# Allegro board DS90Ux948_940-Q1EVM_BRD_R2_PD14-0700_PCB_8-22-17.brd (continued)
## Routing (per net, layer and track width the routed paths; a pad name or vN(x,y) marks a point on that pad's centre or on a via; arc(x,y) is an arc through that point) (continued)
BISTC: length 139.4
  TOP w0.178: U1.4 35.65,75.16 34.88,74.39 30.78,74.39 27.86,71.48 27.86,54.41 22.73,49.28 22.73,41.45 26.34,37.85 60.38,37.85 63.27,40.74 63.27,43.84 J14.4 65.66,43.94 65.66,42.19 77.32,30.53 77.32,24.66 S3.2 79.62,22.36 83.58,22.36 90.04,28.83 90.04,31.5
  TOP w0.254: R61.1 S3.2
BISTEN: length 120.6
  TOP w0.178: S3.1 80.54,23.5 79.78,24.26 79.78,30.28 68.22,41.83 68.22,45.52 67.28,46.46 63.35,46.46 J14.2 56.64,39.75 26.29,39.75 24.51,41.53 24.51,49.66 29.15,54.29 29.15,71.23 31.83,73.91 35.03,73.91 36.15,75.04 U1.5
  TOP w0.254: R62.1 S3.1
CAPI2S: length 3.4
  TOP w0.178: U1.2 34.65,75.75 34.37,75.46 v1(33.73,75.46)
  BOTTOM w0.508: v1(33.73,75.46) 33.63,75.56 C10.2
CLK1+: length 79
  TOP w0.152: U1.36 40.15,90.56 arc(40.29,91.27) 40.7,91.87 40.76,91.93 arc(41.23,92.24) 41.78,92.35 41.91,92.35 arc(42.33,92.44) 42.69,92.68 42.75,92.74 arc(42.97,93.07) 43.05,93.46 arc(43.08,93.62) 43.17,93.75 R89.2 43.22,94.26 arc(43.09,94.44) 43.05,94.66 43.05,94.94 arc(43.16,95.48) 43.47,95.94 43.63,96.11 44.04,96.51 arc(44.55,96.86) 45.16,96.98 58.32,96.98 arc(61.45,96.36) 64.1,94.58 67.16,91.52 arc(67.99,90.29) 68.28,88.83 68.28,84.37 arc(68.44,83.55) 68.9,82.86 arc(69.59,82.4) 70.41,82.24 80.08,82.24 arc(81.03,82.42) 81.83,82.96 arc(82.36,83.76) 82.55,84.7 82.55,86.79 arc(82.81,88.12) 83.56,89.24 83.62,89.29 arc(85.03,90.24) 86.7,90.57 92.41,90.57 arc(92.46,90.57) 92.5,90.56 arc(92.63,90.51) 92.74,90.43 arc(92.82,90.31) 92.85,90.16 92.85,89.97 arc(92.82,89.82) 92.74,89.7 92.71,89.67 arc(92.56,89.57) 92.38,89.54 J15.15
CLK1-: length 79
  TOP w0.152: 93.85,92.08 93.09,91.31 arc(92.83,91.14) 92.52,91.08 92.06,91.08 92.06,91.08 86.7,91.08 arc(84.84,90.71) 83.26,89.65 83.2,89.6 arc(82.34,88.31) 82.04,86.79 82.04,84.7 arc(81.89,83.95) 81.47,83.32 arc(80.83,82.89) 80.08,82.74 70.41,82.74 arc(69.79,82.87) 69.26,83.22 arc(68.91,83.75) 68.79,84.37 68.79,88.83 arc(68.46,90.48) 67.52,91.88 64.46,94.94 arc(61.64,96.82) 58.32,97.49 45.16,97.49 arc(44.36,97.33) 43.68,96.87 43.11,96.3 arc(42.69,95.68) 42.54,94.94 42.54,94.69 arc(42.49,94.44) 42.36,94.24 R89.1 42.42,93.75 arc(42.51,93.62) 42.54,93.46 arc(42.5,93.26) 42.39,93.1 42.33,93.03 arc(42.14,92.91) 41.91,92.86 41.78,92.86 arc(41.03,92.71) 40.4,92.29 40.34,92.23 arc(39.82,91.46) 39.64,90.56 39.64,85.95 U1.37
CLK2+: length 64.4
  TOP w0.152: U1.23 42.31,80.78 45.27,80.78 arc(45.84,80.67) 46.33,80.35 47.15,79.52 arc(47.33,79.26) 47.39,78.95 47.39,78.18 arc(47.72,77.38) 48.53,77.05 48.65,77.05 arc(48.88,77) 49.06,76.88 R95.2 49.51,76.87 arc(49.7,77) 49.93,77.05 53.05,77.05 arc(53.22,77.03) 53.38,76.98 arc(53.85,76.73) 54.26,76.39 55.24,75.41 arc(55.4,75.17) 55.46,74.88 55.46,74.72 arc(55.75,73.26) 56.58,72.01 63.75,64.84 65.3,63.3 65.92,62.68 69.84,58.76 arc(75.02,55.3) 81.13,54.08 86.7,54.08 arc(87.49,54.24) 88.17,54.69 arc(88.52,54.93) 88.94,55.01 91.21,55.01 91.71,55.01 91.87,55.01 arc(91.92,55.01) 91.97,55 arc(92.1,54.95) 92.21,54.87 arc(92.29,54.75) 92.32,54.6 92.32,54.41 arc(92.29,54.26) 92.21,54.14 92.18,54.11 arc(92.03,54.01) 91.85,53.98 J16.15
CLK2-: length 64.4
  TOP w0.152: U1.24 42.31,81.29 45.27,81.29 arc(46.04,81.14) 46.69,80.71 47.51,79.88 arc(47.8,79.45) 47.9,78.95 47.9,78.18 arc(48.08,77.74) 48.53,77.55 48.69,77.55 arc(48.88,77.59) 49.04,77.7 R95.1 49.51,77.73 49.52,77.72 arc(49.7,77.6) 49.92,77.55 53.05,77.55 arc(53.32,77.53) 53.57,77.45 arc(54.13,77.15) 54.62,76.75 55.6,75.77 arc(55.87,75.36) 55.97,74.88 55.97,74.72 55.97,74.72 arc(56.22,73.45) 56.94,72.37 57.86,71.45 60.29,69.02 70.2,59.12 arc(75.21,55.77) 81.13,54.59 86.7,54.59 arc(87.3,54.71) 87.81,55.05 arc(88.33,55.4) 88.94,55.52 91.21,55.52 91.54,55.52 91.93,55.52 91.93,55.52 92.39,55.52 arc(92.7,55.58) 92.97,55.75 J16.14
D0+: length 79
  TOP w0.152: J15.3 92.38,104.78 arc(92.56,104.81) 92.71,104.91 92.74,104.94 arc(92.82,105.06) 92.85,105.21 92.85,105.4 arc(92.82,105.55) 92.74,105.67 arc(92.63,105.75) 92.5,105.8 arc(92.46,105.81) 92.41,105.81 89.41,105.81 arc(87.52,105.43) 85.92,104.36 arc(84.44,103.38) 82.7,103.03 40.71,103.03 arc(39.02,102.69) 37.59,101.74 33.18,97.32 32.78,96.93 arc(32.53,96.56) 32.44,96.11 32.44,94.73 arc(32.5,94.45) 32.66,94.21 R80.2 32.59,93.77 arc(32.48,93.62) 32.44,93.43 32.44,93.11 arc(32.51,92.77) 32.7,92.48 33.28,91.9 arc(33.55,91.72) 33.87,91.66 arc(34.47,91.54) 34.98,91.2 35.63,90.55 36.72,89.45 arc(37.04,88.97) 37.16,88.41 37.16,85.94 U1.42
D0-: length 79
  TOP w0.152: U1.43 36.65,85.94 36.65,88.41 arc(36.57,88.78) 36.36,89.09 35.27,90.19 34.62,90.84 arc(34.27,91.07) 33.87,91.15 arc(33.36,91.25) 32.93,91.54 32.34,92.12 arc(32.04,92.58) 31.94,93.11 31.94,93.44 arc(31.9,93.62) 31.8,93.77 R80.1 31.8,94.28 arc(31.9,94.44) 31.94,94.62 31.94,96.11 arc(32.06,96.75) 32.42,97.29 32.82,97.68 33.37,98.23 37.23,102.1 arc(38.83,103.16) 40.71,103.54 82.7,103.54 arc(84.24,103.85) 85.56,104.72 85.56,104.72 arc(87.32,105.9) 89.41,106.32 92.06,106.32 92.06,106.32 92.52,106.32 arc(92.83,106.38) 93.09,106.55 93.85,107.31
D1+: length 79
  TOP w0.152: U1.40 38.15,89.53 arc(37.99,90.34) 37.53,91.03 36.5,92.06 arc(36.12,92.64) 35.98,93.32 35.98,93.42 arc(36.02,93.62) 36.13,93.78 R86.2 36.14,94.26 arc(36.02,94.44) 35.98,94.65 35.98,95.34 arc(36.15,96.18) 36.62,96.89 39.86,100.13 arc(41.09,100.95) 42.54,101.24 66.02,101.24 arc(67.12,101.02) 68.05,100.4 69.98,98.47 arc(70.63,97.5) 70.85,96.36 70.85,95.74 arc(70.97,95.16) 71.3,94.67 71.57,94.4 arc(72.36,93.87) 73.29,93.69 77.99,93.69 arc(79.53,93.99) 80.84,94.87 86.19,100.22 arc(86.76,100.6) 87.43,100.73 92.41,100.73 arc(92.46,100.73) 92.5,100.72 arc(92.63,100.67) 92.74,100.59 arc(92.82,100.47) 92.85,100.32 92.85,100.13 arc(92.82,99.98) 92.74,99.86 92.71,99.83 arc(92.56,99.73) 92.38,99.7 J15.7
D1-: length 79
  TOP w0.152: U1.41 37.64,85.95 37.64,89.53 arc(37.52,90.15) 37.17,90.67 36.14,91.7 arc(35.65,92.44) 35.47,93.32 35.47,93.4 arc(35.43,93.61) 35.31,93.8 R86.1 35.27,94.22 arc(35.42,94.44) 35.47,94.71 35.47,95.34 arc(35.68,96.38) 36.26,97.25 39.5,100.49 arc(40.89,101.42) 42.54,101.75 66.02,101.75 arc(67.32,101.49) 68.41,100.76 70.34,98.83 arc(71.1,97.7) 71.36,96.36 71.36,95.74 arc(71.44,95.35) 71.65,95.03 71.93,94.76 arc(72.55,94.34) 73.29,94.19 77.99,94.19 arc(79.34,94.46) 80.48,95.23 85.84,100.58 arc(86.57,101.07) 87.43,101.24 92.06,101.24 92.06,101.24 92.52,101.24 arc(92.83,101.3) 93.09,101.47 93.85,102.24
D2+: length 79
  TOP w0.152: U1.38 39.15,92.07 arc(39.17,92.16) 39.21,92.25 arc(39.43,92.59) 39.51,92.99 39.51,93.43 arc(39.55,93.62) 39.66,93.77 R88.2 39.67,94.27 arc(39.55,94.44) 39.51,94.64 39.51,94.83 arc(39.65,95.5) 40.02,96.06 40.49,96.53 42.55,98.58 arc(43.1,98.95) 43.75,99.08 60.37,99.08 arc(62.43,98.67) 64.17,97.5 69.68,92 arc(70.74,90.4) 71.12,88.53 71.12,87.95 arc(71.76,86.4) 73.31,85.75 77.97,85.75 arc(78.87,85.93) 79.63,86.44 arc(80.14,87.2) 80.32,88.1 80.32,88.69 arc(80.6,90.11) 81.41,91.32 83.69,93.6 arc(85.96,95.12) 88.64,95.65 92.41,95.65 arc(92.46,95.65) 92.5,95.64 arc(92.63,95.59) 92.74,95.51 arc(92.82,95.39) 92.85,95.24 92.85,95.05 arc(92.82,94.9) 92.74,94.78 92.71,94.75 arc(92.56,94.65) 92.38,94.62 J15.11
D2-: length 79
  TOP w0.152: 93.85,97.16 93.09,96.39 arc(92.83,96.22) 92.52,96.16 92.06,96.16 92.06,96.16 88.64,96.16 arc(85.77,95.59) 83.33,93.96 81.05,91.68 arc(80.14,90.31) 79.81,88.69 79.81,88.1 arc(79.67,87.4) 79.27,86.8 arc(78.68,86.4) 77.97,86.26 73.31,86.26 arc(72.12,86.75) 71.63,87.95 71.63,88.53 arc(71.21,90.6) 70.04,92.35 64.53,97.86 arc(62.62,99.14) 60.37,99.59 43.75,99.59 arc(42.9,99.42) 42.19,98.94 40.13,96.88 39.66,96.42 arc(39.18,95.69) 39.01,94.83 39.01,94.67 arc(38.96,94.44) 38.83,94.25 R88.1 38.85,93.79 arc(38.97,93.61) 39.01,93.41 39.01,92.99 arc(38.96,92.79) 38.85,92.61 arc(38.7,92.38) 38.64,92.12 38.64,85.95 U1.39
D3+: length 79
  TOP w0.152: U1.34 41.15,88.98 arc(41.26,89.53) 41.57,90 41.59,90.02 arc(42.29,90.49) 43.12,90.65 44.28,90.65 arc(45.07,90.81) 45.74,91.26 46.05,91.56 arc(46.44,92.16) 46.58,92.87 46.58,93.39 arc(46.63,93.61) 46.76,93.8 R90.2 46.72,94.29 arc(46.62,94.44) 46.58,94.61 46.58,94.72 arc(46.78,95.18) 47.25,95.38 56.78,95.38 arc(59.18,94.9) 61.22,93.54 64.99,89.77 arc(65.58,88.88) 65.79,87.83 65.79,80.74 arc(66.01,79.65) 66.63,78.73 arc(67.55,78.11) 68.63,77.9 82.25,77.9 arc(83.93,78.59) 84.62,80.26 84.62,82.7 arc(84.83,83.77) 85.44,84.67 arc(86.34,85.28) 87.41,85.49 92.41,85.49 arc(92.46,85.49) 92.5,85.48 arc(92.63,85.43) 92.74,85.35 arc(92.82,85.23) 92.85,85.08 92.85,84.89 arc(92.82,84.74) 92.74,84.62 92.71,84.59 arc(92.56,84.49) 92.38,84.46 J15.19
D3-: length 79
  TOP w0.152: 93.85,87 93.09,86.23 arc(92.83,86.06) 92.52,86 92.06,86 92.06,86 87.41,86 arc(86.15,85.75) 85.08,85.03 arc(84.36,83.96) 84.11,82.7 84.11,80.26 arc(83.57,78.95) 82.25,78.4 68.63,78.4 arc(67.74,78.58) 66.98,79.09 arc(66.48,79.84) 66.3,80.74 66.3,87.83 arc(66.05,89.07) 65.35,90.13 61.58,93.89 arc(59.38,95.37) 56.78,95.89 47.25,95.89 arc(46.42,95.54) 46.08,94.72 46.08,94.62 arc(46.04,94.44) 45.94,94.29 45.86,94.21 R90.1 45.9,93.81 arc(46.03,93.61) 46.08,93.38 46.08,92.86 arc(45.98,92.35) 45.69,91.92 45.38,91.62 arc(44.88,91.28) 44.28,91.16 43.12,91.16 arc(42.1,90.96) 41.24,90.38 41.22,90.36 arc(40.79,89.73) 40.64,88.98 40.64,85.95 U1.35
D4+: length 64.4
  TOP w0.152: U1.29 42.31,83.78 45.04,83.78 arc(45.98,83.97) 46.77,84.5 47.15,84.88 47.71,85.44 arc(48.06,85.96) 48.18,86.58 48.18,87.16 arc(48.33,87.51) 48.68,87.65 arc(48.88,87.61) 49.04,87.5 R92.2 49.51,87.48 arc(49.7,87.61) 49.93,87.65 57.98,87.65 arc(58.11,87.64) 58.24,87.6 58.47,87.5 arc(58.81,87.32) 59.11,87.08 59.98,86.2 60.3,85.89 60.76,85.42 arc(61.19,84.79) 61.34,84.04 61.34,82.89 arc(61.78,80.64) 63.06,78.73 69.49,72.29 71.47,70.32 71.51,70.28 arc(72.96,69.31) 74.66,68.97 84.94,68.97 arc(85.63,69.11) 86.22,69.5 arc(87.05,70.05) 88.02,70.25 91.87,70.25 arc(91.92,70.25) 91.97,70.24 arc(92.1,70.19) 92.21,70.11 arc(92.29,69.99) 92.32,69.84 92.32,69.65 arc(92.29,69.5) 92.21,69.38 92.18,69.35 arc(92.03,69.25) 91.85,69.22 J16.3
D4-: length 64.4
  TOP w0.152: J16.2 92.97,70.99 arc(92.7,70.82) 92.39,70.76 91.93,70.76 91.93,70.76 88.02,70.76 arc(86.85,70.52) 85.86,69.86 arc(85.44,69.58) 84.94,69.48 74.66,69.48 arc(73.15,69.78) 71.87,70.64 63.42,79.09 arc(62.25,80.83) 61.84,82.89 61.84,84.04 arc(61.66,84.98) 61.12,85.78 60.66,86.25 60.34,86.56 59.47,87.44 arc(59.09,87.74) 58.67,87.97 58.43,88.07 arc(58.21,88.14) 57.98,88.16 49.87,88.16 arc(49.7,88.19) 49.56,88.29 R92.1 49.03,88.3 arc(48.88,88.2) 48.7,88.16 48.68,88.16 arc(47.97,87.87) 47.68,87.16 47.68,86.58 arc(47.59,86.16) 47.35,85.8 46.79,85.24 46.41,84.86 arc(45.78,84.44) 45.04,84.29 42.31,84.29 U1.30
D5+: length 64.4
  TOP w0.152: J16.7 91.85,64.14 arc(92.03,64.17) 92.18,64.27 92.21,64.3 arc(92.29,64.42) 92.32,64.57 92.32,64.76 arc(92.29,64.91) 92.21,65.03 arc(92.1,65.11) 91.97,65.16 arc(91.92,65.17) 91.87,65.17 90.68,65.17 arc(89.86,65.01) 89.16,64.54 87.35,62.73 arc(86.28,62.01) 85.02,61.76 77.17,61.76 arc(75.99,62) 74.99,62.67 61.33,76.32 arc(60.19,78.03) 59.79,80.05 arc(59.53,81.35) 58.79,82.44 58.27,82.97 arc(57,83.82) 55.51,84.12 49.98,84.12 arc(49.71,84.06) 49.48,83.91 R93.2 49.02,83.99 49.02,83.99 arc(48.88,84.08) 48.72,84.12 arc(48.38,84.05) 48.1,83.86 47.63,83.39 arc(46.96,82.94) 46.16,82.78 42.31,82.78 U1.27
D5-: length 64.4
  TOP w0.152: U1.28 42.31,83.29 46.16,83.29 arc(46.76,83.41) 47.27,83.75 47.74,84.22 arc(48.19,84.52) 48.72,84.62 48.74,84.62 arc(48.88,84.65) 49,84.73 R93.1 49.51,84.8 arc(49.7,84.67) 49.93,84.62 55.51,84.62 arc(57.19,84.29) 58.63,83.33 59.15,82.8 arc(60,81.54) 60.29,80.05 arc(60.66,78.23) 61.69,76.68 75.35,63.03 arc(76.18,62.47) 77.17,62.27 85.02,62.27 arc(86.09,62.48) 86.99,63.09 88.8,64.9 arc(89.66,65.48) 90.68,65.68 91.93,65.68 91.93,65.68 92.39,65.68 arc(92.7,65.74) 92.97,65.91 J16.6
D6+: length 64.4
  TOP w0.152: U1.25 42.31,81.78 46.82,81.78 arc(46.96,81.76) 47.09,81.67 47.94,80.82 arc(48.2,80.64) 48.51,80.58 48.63,80.58 arc(48.87,80.53) 49.08,80.4 R94.2 49.49,80.38 arc(49.71,80.53) 49.97,80.58 54.37,80.58 arc(55.19,80.42) 55.88,79.96 57.29,78.55 57.39,78.45 arc(57.59,78.15) 57.66,77.8 57.66,76.62 arc(57.75,75.85) 58.01,75.13 arc(58.29,74.68) 58.63,74.28 58.71,74.2 73.85,59.05 arc(75.88,57.7) 78.27,57.22 85.54,57.22 arc(86.51,57.42) 87.34,57.97 88.85,59.48 arc(89.53,59.93) 90.32,60.09 91.87,60.09 arc(91.92,60.09) 91.97,60.08 arc(92.1,60.03) 92.21,59.95 arc(92.29,59.83) 92.32,59.68 92.32,59.49 arc(92.29,59.34) 92.21,59.22 92.18,59.19 arc(92.03,59.09) 91.85,59.06 J16.11
D6-: length 64.4
  TOP w0.152: U1.26 42.31,82.29 46.82,82.29 arc(47.16,82.22) 47.45,82.03 48.3,81.18 arc(48.4,81.11) 48.51,81.09 48.69,81.09 arc(48.88,81.13) 49.03,81.23 R94.1 49.51,81.27 arc(49.7,81.14) 49.94,81.09 54.37,81.09 arc(55.38,80.89) 56.24,80.31 57.65,78.91 57.75,78.81 arc(58.06,78.34) 58.17,77.8 58.17,76.62 arc(58.38,75.54) 58.99,74.64 63.28,70.34 74.21,59.41 arc(76.07,58.17) 78.27,57.73 85.54,57.73 arc(86.32,57.89) 86.98,58.32 88.49,59.84 arc(89.33,60.4) 90.32,60.6 91.93,60.6 91.93,60.6 92.39,60.6 arc(92.7,60.66) 92.97,60.83 J16.10
D7+: length 64.4
  TOP w0.152: U1.21 42.31,79.78 44.41,79.78 arc(44.66,79.74) 44.86,79.6 45.21,79.25 arc(45.73,78.48) 45.91,77.57 45.91,77.12 arc(46.19,75.67) 47.01,74.45 47.01,74.45 47.66,73.8 arc(47.98,73.59) 48.36,73.51 48.66,73.51 arc(48.88,73.47) 49.06,73.34 R96.2 49.52,73.35 49.53,73.36 arc(49.7,73.47) 49.9,73.51 arc(51.06,73.28) 52.05,72.62 65.36,59.32 arc(75.75,52.37) 88.02,49.93 91.87,49.93 arc(91.92,49.93) 91.97,49.92 arc(92.1,49.87) 92.21,49.79 arc(92.29,49.67) 92.32,49.52 92.32,49.33 arc(92.29,49.18) 92.21,49.06 92.18,49.03 arc(92.03,48.93) 91.85,48.9 J16.19
D7-: length 64.4
  TOP w0.152: J16.18 92.97,50.67 arc(92.7,50.5) 92.39,50.44 91.93,50.44 91.93,50.44 91.87,50.44 90.41,50.44 88.02,50.44 arc(75.95,52.84) 65.71,59.67 52.41,72.98 arc(51.26,73.75) 49.9,74.02 49.9,74.02 arc(49.7,74.06) 49.53,74.17 R96.1 49.06,74.19 arc(48.88,74.06) 48.66,74.02 48.36,74.02 arc(48.18,74.06) 48.02,74.16 47.37,74.81 arc(46.66,75.87) 46.42,77.12 46.42,77.57 arc(46.2,78.67) 45.57,79.61 45.22,79.96 arc(44.85,80.2) 44.41,80.29 42.31,80.29 U1.22
D_GPIO0: length 52.4
  TOP w0.178: U1.19 43.92,78.79 44.86,77.85 44.86,75.13 45.72,74.27 45.72,72.14 66.78,51.08 72.36,51.08 77.22,46.23 J14.14
D_GPIO1: length 49.6
  TOP w0.178: U1.18 43.68,78.29 44.45,77.52 44.45,74.8 45.21,74.04 45.21,71.53 66.17,50.57 69.82,50.57 74.68,45.72 J14.12
D_GPIO2: length 47.4
  TOP w0.178: U1.17 43.45,77.79 44.02,77.22 44.02,74.45 44.7,73.76 44.7,70.59 65.28,50.02 68.09,50.02 72.14,45.97 J14.10
D_GPIO3: length 45
  TOP w0.178: J14.8 69.6,46.71 67.64,48.67 65.23,48.67 44.36,69.54 44.36,73.15 41.65,75.86 U1.16
DM: length 31.6
  TOP w0.152: R66.2 16.72,143.52 20.82,143.52 26.54,137.8 30.26,137.8 38.51,129.54 38.51,128.55 38.05,128.08 37.51,128.08 37.27,127.84 U4.64
DOUT+: length 6.3
  TOP w0.152: C9.2 28.26,76.87 arc(28.41,76.76) 28.6,76.73 28.7,76.73 arc(29.12,76.81) 29.47,77.05 29.62,77.2 30.62,78.2 arc(31.28,78.64) 32.06,78.79 33.5,78.79 U1.62
DOUT-: length 6.3
  TOP w0.152: U1.63 33.5,78.28 32.06,78.28 arc(31.48,78.17) 30.98,77.84 29.83,76.69 arc(29.31,76.34) 28.7,76.22 28.48,76.22 arc(28.38,76.2) 28.3,76.15 C11.2
DP: length 33.8
  TOP w0.152: R67.2 17.24,143.01 18.21,143.01 18.39,142.83 18.39,142.22 18.54,142.07 18.82,142.07 19,142.25 19,142.82 19.18,143.01 20.61,143.01 26.33,137.29 30.05,137.29 38.01,129.33 38.01,128.76 37.84,128.59 37.51,128.59 37.27,128.84 U4.62
  TOP w0.178: R69.1 16.27,141.87 arc(16.25,141.93) R67.2
GPIO0: length 79.4
  TOP w0.178: U1.7 37.15,74.5 36.68,74.03 35.91,74.03 35.31,73.43 32.61,73.43 30.26,71.08 30.26,51.22 26.42,47.37 J17.2 ; v1(15.44,14.32) R2.2 15.44,11.06 JP2.1
  BOTTOM w0.178: v1(15.44,14.32) 17.12,16 18.8,16 24.64,21.84 24.64,43.31 J17.2
GPIO0/I2C(SDA): length 41.4
  TOP w0.178: U6.1 69.23,136.54 69.23,136.54 68.78,136.09 v1(68.68,136.09) ; U4.46 45.43,132.7 49.28,136.55 49.28,138.05 J12.1
  BOTTOM w0.178: v1(68.68,136.09) 68.43,136.35 68.43,141.11 66.26,143.28 61.14,143.28 55.63,137.77 49.56,137.77 J12.1
GPIO1: length 36.2
  TOP w0.178: U1.8 37.65,76.64 37.65,74.2 36.7,73.25 35.79,73.25 32.61,70.08 32.61,48.74 J17.4
GPIO1/I2C(SCL): length 31.6
  TOP w0.178: J12.2 44.93,134.21 U4.47 ; U6.8 67.92,140.11 v1(67.89,140.13)
  BOTTOM w0.178: v1(67.89,140.13) 65.57,142.46 61.66,142.46 56.46,137.26 47.98,137.26 J12.2
GPIO2/SPI(SCLK): length 20.6
  TOP w0.178: v1(46.6,133.06) 46.6,133.04 45.93,132.37 U4.45 ; U5.12 51.59,140.41 50.88,141.12 46.76,141.12 J12.3
  BOTTOM w0.178: J12.3 45.21,139.56 44.03,138.37 44.03,136.43 46.6,133.86 v1(46.6,133.06)
GPIO3/PWM2: length 16.8
  TOP w0.178: U4.33 v1(51.18,125.84) 51.19,125.82 R73.1
  BOTTOM w0.178: J12.4 51.18,131.06 v1(51.18,125.84)
GPIO4/SPI(SIMO)/UART(TXD): length 25.3
  TOP w0.178: U5.11 52.14,141.06 51.41,141.78 41.82,141.78 40.13,140.1 J12.7 ; U4.52 42.43,132.88 v1(41.55,133.76)
  BOTTOM w0.178: J12.7 41.55,138.15 v1(41.55,133.76)
GPIO5/SPI(SOMI)/UART(RXD): length 27.7
  TOP w0.178: U4.51 42.93,134.23 J12.8 38.85,138.32 38.85,140.01 41.44,142.6 51.92,142.6 52.8,141.71 U5.10
GPIO6/PWM1/SPI(CS): length 43.4
  TOP w0.178: U4.29 54.75,123.84 55.96,125.04 55.96,131.6 51.97,135.59 51.97,139.24 52.48,139.76 v1(53.06,139.76) U5.13
  BOTTOM w0.178: v1(53.06,139.76) 50.58,142.24 39.55,142.24 37.59,140.28 J12.9
GPIO7/PWM0: length 29.9
  TOP w0.178: U4.23 v1(51.18,120.84) 51.26,120.76 R74.1
  BOTTOM w0.178: J12.10 37.59,134.43 38.87,133.15 44.7,133.15 45.32,132.53 48.01,132.53 50.37,130.17 50.37,121.64 v1(51.18,120.84)
GPIO11/VEREF+: length 1.8
  TOP w0.178: U4.9 v1(42.43,116.71)
  BOTTOM w0.508: v1(42.43,116.71) 42.42,116.72 C23.2
I2C_SCL: length 137.3
  TOP w0.178: U1.45 35.65,87.5 34.98,88.18 34.98,88.34 33.82,89.5 32.01,89.5 28.5,93.01 28.5,100.74 31.19,103.43 35.59,103.43 38.68,106.52 83.49,106.52 92.33,115.36 92.33,119.46 v1(91.26,120.52) ; v1(71.35,140.56) 70.89,140.11 U6.5
  BOTTOM w0.178: R85.1 v1(91.26,120.52) 91.22,120.56 R82.2 88.86,120.56 88.14,121.28 88.14,133.22 85.85,135.51 78.87,135.51 J19.14 74.93,131.83 74.3,132.46 74.3,137.62 v1(71.35,140.56)
I2C_SDA: length 135
  TOP w0.178: U1.46 35.15,87.38 34.62,87.91 34.62,88.12 33.73,89.01 31.77,89.01 27.69,93.09 27.69,101.22 30.81,104.34 35.27,104.34 38.32,107.4 83.28,107.4 91.34,115.45 v1(91.34,118.62) ; v1(71.25,137.01) U6.4
  BOTTOM w0.178: v1(91.34,118.62) 91.34,118.97 90.81,119.51 87.5,119.51 85.98,121.03 85.98,131.95 84.07,133.86 77.85,133.86 76.58,132.59 76.58,131.19 75.82,130.43 74.04,130.43 J19.15 72.64,135.61 v1(71.25,137.01) ; v1(91.34,118.62) R84.1 ; v1(91.34,118.62) 91.17,118.45 R81.2
I2S_CLK: length 38.4
  TOP w0.178: U1.13 40.15,74.33 42.6,71.87 42.6,67.6 43.05,67.15 43.05,44.45 43.76,43.74 45.39,43.74 J17.18
I2S_DA: length 32.9
  TOP w0.178: U1.12 39.65,74.17 41.53,72.29 41.53,45.21 J17.14
I2S_DB: length 32.9
  TOP w0.178: J17.12 39.15,45.12 39.15,69.33 40.18,70.37 40.18,73.13 39.15,74.16 U1.11
I2S_DC: length 39.6
  TOP w0.178: J17.6 32.79,43.79 34.54,43.79 35.28,44.53 35.28,45.62 38.65,48.99 38.65,69.39 39.83,70.57 39.83,72.77 38.65,73.95 U1.10
I2S_DD: length 34.1
  TOP w0.178: U1.9 38.15,74.24 37.72,73.8 37.72,72.47 36.91,71.65 36.4,71.65 34.04,69.29 J17.8
I2S_WC: length 33.5
  TOP w0.178: J17.16 43.94,45.34 43.94,67.3 43.19,68.05 43.19,72.99 40.65,75.53 U1.14
IDX: length 153.7
  TOP w0.178: v1(34.04,87.99) 34.04,88.01 34.65,87.4 U1.47 ; v1(70.85,20.19) 70.85,29.53 67.86,32.52 S4.16 S4.14 S4.12 S4.10 S4.8 S4.6 S4.4 S4.2 v1(47.78,32.52)
  BOTTOM w0.178: v1(47.78,32.52) 45.59,30.33 45.59,20.45 44.07,18.92 39.19,18.92 30.28,27.84 30.28,48.08 23.95,54.41 23.95,62.15 18.67,67.44 18.67,75.11 17.32,76.45 17.32,87.3 20.7,90.68 29.21,90.68 32.21,87.68 33.73,87.68 v1(34.04,87.99) ; C104.2 v1(70.85,20.19)
INTB: length 30.6
  TOP w0.178: U5.3 v1(61.48,139.11)
  BOTTOM w0.178: J19.9 75.95,128.52 70.74,128.52 68.71,130.56 68.71,132.46 67.18,133.99 62.05,133.99 60.58,135.46 60.58,138.18 61.48,139.07 v1(61.48,139.11)
INTB_CTRL: length 20.9
  TOP w0.178: R74.2 55.1,120.76 56.41,122.07 56.41,138.35 55.66,139.11 U5.14
LOCK: length 67.3
  TOP w0.178: U1.1 34.15,76.86 33.93,76.64 33.62,76.64 31.71,74.72 30.14,74.72 27.19,71.77 27.19,57.42 20.83,51.05 20.83,27.94 15.86,22.97 R1.2 15.86,20.87 16.52,20.21 JP1.1
MCLK: length 35.4
  TOP w0.178: U1.15 41.15,75.81 43.81,73.15 43.81,68.89 49.28,63.42 J17.20
MISO: length 23.3
  TOP w0.178: U5.6 v1(61.55,141.06)
  BOTTOM w0.178: J19.3 61.34,127.89 60.25,127.89 57.78,130.35 57.78,137.41 61.43,141.06 v1(61.55,141.06)
MODE_SEL0: length 105.5
  TOP w0.178: v1(30.25,78.71) 30.51,78.97 31.51,79.29 U1.61 ; v1(70.74,9.45) 70.74,14.43 67.96,17.2 S1.16 S1.14 S1.12 S1.10 S1.8 S1.6 S1.4 S1.2 46.8,17.2 45.59,18.42 45.59,19.3 v1(44.45,20.45)
  BOTTOM w0.178: v1(44.45,20.45) 35.15,29.74 35.15,47.4 26.7,55.85 26.7,72.47 29.11,74.88 29.11,77.57 v1(30.25,78.71) ; C102.2 v1(70.74,9.45)
MODE_SEL1: length 128.5
  TOP w0.178: U1.50 32.1,84.79 31.17,85.73 v1(31.17,86.87) ; v1(21.34,9.45) 21.92,10.03 21.92,14.33 24.59,17 S2.2 S2.4 S2.6 S2.8 S2.10 S2.12 S2.14 S2.16 43.43,19.3 v1(42.8,19.94)
  BOTTOM w0.178: v1(42.8,19.94) 32.61,30.12 32.61,48.06 25.25,55.42 25.25,63.03 19.66,68.63 19.66,75.03 17.81,76.89 17.81,86.32 21.25,89.76 28.68,89.76 31.17,87.28 v1(31.17,86.87) ; C103.2 v1(21.34,9.45)
MOSI: length 24.3
  TOP w0.178: U5.7 v1(61.85,141.71)
  BOTTOM w0.178: v1(61.85,141.71) 62.12,141.43 62.12,140.74 58.55,137.16 58.55,135.38 61.09,132.84 61.09,130.68 J19.4
PDB: length 274.3
  TOP w0.178: v1(32.78,88.35) 32.93,88.35 34.15,87.12 U1.48 ; R120.1 v1(62.52,134.73) ; S3.3 78.1,21.34 87.7,21.34 SW1.2 89.53,23.17 C12.1
  TOP w0.254: R60.1 S3.3
  BOTTOM w0.178: v1(62.52,134.73) 68.04,134.73 68.78,133.99 70.23,133.99 71.37,132.84 71.37,131.27 73.1,129.54 76.23,129.54 77.72,131.04 J19.13 80.26,129.29 83.19,129.29 84.71,127.76 84.71,122.43 82.8,120.52 80.14,120.52 70.23,110.62 43.18,110.62 33.4,100.84 33.4,97.66 32.64,96.9 32.64,92.33 33.78,91.19 33.78,89.28 32.85,88.35 v1(32.78,88.35) 29.66,91.47 20.4,91.47 16.84,87.91 16.84,75.95 17.96,74.83 17.96,66.31 22.06,62.2 22.06,54.34 27.86,48.53 27.86,27.31 41,14.17 68.91,14.17 75.95,21.21 S3.3
PDB_CTRL: length 13.5
  TOP w0.178: v1(54.76,136.14) 54.73,136.18 U5.16 ; v1(55.14,125.86) 55.11,125.82 R73.2
  BOTTOM w0.178: v1(54.76,136.14) 55.72,135.19 55.72,126.43 v1(55.14,125.86)
PUR: length 27.3
  TOP w0.178: U4.63 35.42,128.34 32.89,130.86 32.89,132.46 30.86,134.49 SW2.1 18.32,135.6 17.52,136.41 R71.1 R69.2
RINA+: length 27.6
  TOP w0.152: 9.25,83.29 17.78,83.29 19.37,83.29 ; L1.3 20.92,83.29 ; 20.92,83.29 19.37,83.29 ; 20.92,83.29 29.29,83.29 arc(29.4,83.31) 29.49,83.37 C3.1 ; 19.37,83.29 L1.4
  TOP w0.178: J1.2 5.98,82.77 arc(6.55,83.16) 7.23,83.29 9.15,83.29
  BOTTOM w0.178: J1.2 5.26,82.27 arc(4.93,82.13) 4.8,81.81 4.8,81.41 arc(4.72,81.22) 4.52,81.13 4.38,81.13 arc(4.26,81.19) 4.2,81.31 R37.2
RINA-: length 27.2
  TOP w0.152: 19.37,82.78 9.24,82.78 ; 19.37,82.78 20.92,82.78 ; 19.37,82.78 L1.1 ; L1.2 20.92,82.78 ; 20.92,82.78 29.29,82.78 arc(29.4,82.76) 29.49,82.7 C4.1
  TOP w0.178: J1.4 7.47,80.64 arc(7.52,80.87) 7.65,81.07 arc(7.85,81.21) 8.09,81.25 8.27,81.25 arc(8.42,81.28) 8.55,81.37 arc(8.63,81.5) 8.66,81.65 8.66,82.3 arc(8.8,82.63) 9.13,82.77
  BOTTOM w0.178: J1.4 R38.2
RINB+: length 31.2
  TOP w0.152: 19.37,80.79 10.81,80.79 arc(9.95,80.62) 9.22,80.13 8.67,79.59 8.67,79.57 8.57,79.47 arc(8.42,79.37) 8.26,79.34 6.91,79.34 arc(6.66,79.41) 6.5,79.62 arc(6.5,79.63) 6.49,79.64 arc(6.48,79.71) 6.47,79.78 ; 19.37,80.79 20.92,80.79 ; 19.37,80.79 L2.4 ; 20.92,80.79 29.32,80.79 arc(29.4,80.81) 29.46,80.85 C6.1 ; 20.92,80.79 L2.3
  TOP w0.178: J1.1 6.68,81.47 arc(6.52,81.24) 6.47,80.97 6.47,79.94
  BOTTOM w0.178: R63.2 8.66,80.66 arc(8.48,80.73) 8.4,80.91 8.4,82.4 arc(8.32,82.6) 8.12,82.68 7.69,82.68 arc(7.54,82.62) 7.47,82.47 J1.1
RINB-: length 31.7
  TOP w0.152: 20.92,80.28 19.37,80.28 ; 20.92,80.28 29.32,80.28 arc(29.4,80.27) 29.46,80.23 C7.1 ; 20.92,80.28 L2.2 ; 19.37,80.28 10.81,80.28 arc(10.14,80.15) 9.58,79.78 9.03,79.23 9.02,79.23 8.91,79.12 arc(8.61,78.92) 8.26,78.85 6.62,78.85 arc(6.3,78.9) 6.01,79.05 ; 19.37,80.28 L2.1
  TOP w0.178: J1.3 4.91,80.27 arc(4.66,80.17) 4.56,79.92 4.56,79.72 arc(4.6,79.53) 4.7,79.37 arc(4.86,79.26) 5.05,79.23 5.64,79.23 arc(5.78,79.2) 5.9,79.13 arc(5.92,79.11) 5.93,79.1
  BOTTOM w0.178: J1.3 5.86,80.66 arc(6.31,81.32) 6.46,82.1 6.46,82.24 arc(6.61,82.97) R64.2
RST: length 80.7
  TOP w0.178: J21.2 92.05,162.09 R119.1 ; J19.16 70.1,133.6 66.67,137.03 66.67,142.49 67.69,143.51 71.88,143.51 72.77,142.62 74.42,142.62 75.18,143.38 82.42,143.38 86.49,139.32 89.13,139.32 91.8,136.65 96.27,136.65 96.65,137.03 96.65,146.69 J20.2 96.19,149.02 96.19,159.33 95.63,159.89 95.39,159.89 C101.1 95,161.04 94.87,161.16 R119.1 ; SW3.2 96.65,162.09 R119.1
SCLBRD: length 3.4
  TOP w0.178: U4.38 52.27,128.34 R79.1
SDABRD: length 3.2
  TOP w0.178: R78.1 52.64,127.84 U4.37
SPLK: length 23.6
  TOP w0.178: U5.5 63.56,140.41 65.02,138.94 65.02,136.65 66.29,135.38 66.29,129.9 71.98,124.21 J19.6
SS: length 21.7
  TOP w0.178: U5.4 63.32,139.76 64.13,138.94 64.13,133.73 63.75,133.35 63.75,130.56 J19.5
SW0: length 6.4
  TOP w0.178: S5.2 59.94,121.67 J19.2
SW1: length 16
  TOP w0.178: S5.4 62.48,120.78 64.62,122.91 73.89,122.91 J19.7
SW2: length 16.2
  TOP w0.178: J19.8 75.67,122.15 66.14,122.15 65.02,121.03 S5.6
SW3: length 18.4
  TOP w0.178: S5.8 67.56,120.4 68.63,121.46 80.06,121.46 J19.10
SW4: length 16.1
  TOP w0.178: S5.10 v1(70.1,120.52)
  BOTTOM w0.178: v1(70.1,120.52) 68.71,121.92 68.71,125.6 J19.19
SW5: length 16.1
  TOP w0.178: S5.12 v1(72.64,120.52)
  BOTTOM w0.178: J19.18 71.5,125.35 71.5,121.67 v1(72.64,120.52)
SW6: length 30.4
  TOP w0.178: J19.12 80.26,132.33 81.53,133.6 84.07,133.6 84.96,132.72 84.96,122.3 79.38,116.71 75.82,116.71 75.18,117.35 S5.14
SW7: length 18.2
  TOP w0.178: S5.16 77.72,120.14 77.98,120.4 81.41,120.4 84.2,123.19 84.2,130.43 J19.11
TCK: length 29.8
  TOP w0.178: J11.7 22.76,121.01 25.73,121.01 26.39,120.35 26.39,115.04 28.12,113.31 33.45,113.31 34.47,114.33 34.47,121.26 35.55,122.34 U4.75
TDI: length 31.1
  TOP w0.178: U4.73 35.43,123.34 32.99,120.9 32.99,115.9 31.93,114.83 29.03,114.83 27.84,116.03 27.84,123.34 24.92,126.26 22.58,126.26 J11.3
TDO: length 19.9
  TOP w0.178: U4.72 v1(37.55,123.84)
  BOTTOM w0.178: v1(37.55,123.84) 36.25,125.15 28.3,125.15 24.69,128.75 22.63,128.75 J11.1
TEST: length 62.1
  TOP w0.178: J21.4 90.88,159.46 R118.2 90.88,142.3 J20.7 88.14,140.46 85.6,143 84.45,143 83.31,144.15 75.18,144.15 74.93,144.4 67.06,144.4 65.91,143.26 65.91,136.65 67.56,135 J19.17
TEST1: length 13.4
  TOP w0.178: U4.71 v1(35.28,124.34)
  BOTTOM w0.178: v1(35.28,124.34) 25.79,124.34 J11.8
TMS: length 30.1
  TOP w0.178: U4.74 35.54,122.84 33.83,121.13 33.83,115.16 32.99,114.33 28.47,114.33 27.25,115.54 27.25,121.62 25.1,123.77 22.53,123.77 J11.5
VUSB: length 34.5
  TOP w0.178: U4.66 37.33,126.84 37.85,127.36 v1(37.85,127.38)
  TOP w0.508: v1(12.95,133.12) 12.92,133.15 SW2.2 12.92,135.47 13.6,136.14 C18.1
  BOTTOM w0.508: v1(37.85,127.38) 35.38,127.38 34.87,126.87 34.57,126.87 33.96,126.26 30.3,126.26 23.44,133.12 v1(12.95,133.12)
~RST: length 20.6
  TOP w0.178: v1(35.1,121.11) 35.1,121.31 35.63,121.84 U4.76
  BOTTOM w0.178: v1(35.1,121.11) 32.59,118.59 22.61,118.59 21.36,117.35 J11.11
  BOTTOM w0.508: C22.1 35.79,121.79 v1(35.1,121.11)
  BOTTOM w0.635: J11.11 20.34,117.35 20.22,117.47 R72.1
N15364431: length 4.4
  TOP w0.432: R102.1 34.73,155.92 33.17,157.48 32.45,157.48 32.18,157.74 U7.12
  vias: v1(43.69,166.75) v1(43.94,169.5) v1(45.97,166.75) v1(46.23,169.5) v1(48.26,166.75) v1(48.52,169.5) v1(50.29,166.75) v1(50.55,169.5) v1(56.64,169) v1(56.64,167.85) v1(56.64,165.95) v1(56.64,164.8) v1(60.2,168.91) v1(60.2,167.77) v1(60.2,165.86) v1(60.2,164.72) v1(61.72,169) v1(61.72,168.11)
N15364577:
  vias: v1(30.86,168.73) v1(30.86,167.46) v1(32.77,168.61) v1(32.77,167.34) v1(34.67,168.61) v1(34.67,167.34) v1(34.67,166.07) v1(34.67,164.8) v1(36.58,168.61) v1(36.58,167.34) v1(36.58,166.07) v1(36.58,164.8)
N15364585: length 4
  TOP w0.432: R97.2 32.59,164.27 32.59,162.59 32.3,162.3 U7.19
N15364779: length 4
  TOP w0.432: U7.9 24.17,157.74 23.6,157.18 23.6,155.67 C43.1
N15364847: length 5.1
  TOP w0.432: R101.1 22.41,156.88 23.93,158.39 U7.8
N15364875: length 29.2
  TOP w0.432: U7.7 22.58,159.04 C42.1 21.4,157.86 R100.1 19.62,157.01 18.62,156.01 18.62,152.73 19.41,151.94 30.23,151.94 31.95,153.67 R106.2 32.93,155.73 R102.2
N15364879: length 5.8
  TOP w0.432: C45.2 20.7,159.89 20.89,160.08 C42.2 22.88,160.08 23.26,159.69 U7.6
N15365029: length 1.7
  TOP w0.432: C36.1 31.16,164.33 U7.20
N16848563: length 2.1
  TOP w0.178: U4.20 v1(47.93,116.71)
  BOTTOM w0.508: C29.1 48.13,116.92 v1(47.93,116.71)
N16848714: length 2.2
  TOP w0.254: U4.67 v1(35.31,126.34)
  BOTTOM w0.508: C21.1 35.46,126.49 v1(35.31,126.34)
N16849932: length 6.6
  TOP w0.152: R67.1 14.13,142.37 U3.4 12.31,141.86 11.18,141.86 10.39,142.64 9.84,142.64 9.69,142.49 J10.3
N16849951: length 0.6
  TOP w0.254: U3.6 v1(13.46,143.38)
  vias: v1(10.08,144.21) v1(11.87,145.14) v1(11.91,144.53) v1(12.55,145.17) v1(13.15,145.17)
N16849953: length 6.6
  TOP w0.152: R66.1 14.26,144.28 12.79,144.28 12.43,143.93 12.43,143.74 U3.1 12.06,143.38 10.78,143.38 10.54,143.15 9.84,143.15 9.69,143.29 J10.2
N16930628: length 6.3
  TOP w0.178: U4.15 45.43,116.72 46.15,116 46.99,116 48.63,114.36 Q1.1
N17059131: length 19.1
  TOP w0.178: J20.8 93.93,141.78 93.93,156.53 R118.1
N17075556: length 2.9
  TOP w0.152: C6.2 30.99,80.86 arc(31.06,80.81) 31.15,80.79 33.5,80.79 U1.58
N17075562: length 2.9
  TOP w0.152: C7.2 30.99,80.22 arc(31.06,80.27) 31.15,80.28 33.5,80.28 U1.59
N17075662: length 3.1
  TOP w0.178: v1(31.81,82.29) U1.55
  BOTTOM w0.381: C5.2 32.66,83.14 v1(31.81,82.29)
N17075712: length 2.9
  TOP w0.152: U1.53 33.5,83.29 31.16,83.29 arc(31.06,83.31) 30.98,83.37 C3.2
N17075718: length 2.9
  TOP w0.152: C4.2 30.98,82.71 arc(31.06,82.77) 31.16,82.78 33.5,82.78 U1.54
N17084124: length 1.8
  BOTTOM w0.508: R91.1 J17.10
N17084985: length 50
  BOTTOM w0.152: 12.82,104.82 13.19,104.82 arc(14.01,104.47) 14.35,103.65 14.35,98.41 arc(13.63,94.76) 11.56,91.67 2.4,82.5 arc(2.13,82.1) 2.03,81.62 2.03,80.31 arc(2.37,79.51) 3.17,79.17 3.5,79.17
  BOTTOM w0.178: 3.66,79.16 3.96,79.16 arc(4.26,79.04) 4.38,78.74 R38.1 ; J4.1 9.81,97.14 arc(11.47,97.83) 12.16,99.49 12.16,104.23 arc(12.33,104.64) 12.73,104.8
N17084987: length 50
  BOTTOM w0.152: 12.81,105.32 13.19,105.32 arc(14.37,104.83) 14.86,103.65 14.86,98.41 arc(14.1,94.57) 11.92,91.31 2.76,82.14 arc(2.6,81.9) 2.54,81.62 2.54,80.31 arc(2.73,79.87) 3.17,79.68 3.49,79.68
  BOTTOM w0.178: 3.56,79.69 3.96,79.69 arc(4.13,79.76) 4.2,79.93 R37.1 ; J3.1 9.81,113.02 arc(11.47,112.33) 12.16,110.67 12.16,105.87 arc(12.31,105.49) 12.69,105.34
N17087573: length 48.2
  BOTTOM w0.152: 9.44,83.41 10.03,83.41 arc(11.3,83.16) 12.38,82.44 13.59,81.23 arc(14.5,79.86) 14.83,78.24 14.83,58.89 arc(14.33,57.7) 13.15,57.21 12.77,57.21
  BOTTOM w0.178: R65.1 9.77,49.52 arc(11.43,50.21) 12.12,51.87 12.12,56.67 arc(12.28,57.04) 12.66,57.2 ; 9.35,83.43 8.72,83.43 arc(8.5,83.47) R64.1
N17087575: length 48.2
  BOTTOM w0.152: 12.69,57.72 13.15,57.72 arc(13.98,58.06) 14.32,58.89 14.32,59.3 arc(14.27,59.53) 14.14,59.72 14.09,59.77 arc(13.97,60.06) 14.09,60.35 14.19,60.46 arc(14.29,60.59) 14.32,60.75 14.32,60.85 arc(14.27,61.1) 14.13,61.31 14.1,61.33 arc(13.97,61.66) 14.1,61.98 14.21,62.09 arc(14.32,62.34) 14.21,62.6 14.07,62.74 arc(13.97,62.98) 14.07,63.22 14.2,63.35 arc(14.29,63.48) 14.32,63.63 14.32,72.88 arc(14.29,73.05) 14.19,73.18 arc(14.1,73.32) 14.07,73.48 14.07,73.5 arc(14.11,73.67) 14.2,73.82 arc(14.32,74.09) 14.2,74.37 14.09,74.48 arc(14.02,74.65) 14.09,74.82 14.21,74.94 arc(14.32,75.2) 14.21,75.45 14.11,75.55 arc(14.05,75.71) 14.11,75.87 14.25,76.01 arc(14.32,76.17) 14.25,76.32 14.1,76.47 arc(14.02,76.67) 14.1,76.86 14.23,76.99 arc(14.32,77.21) 14.23,77.42 14.13,77.52 arc(14.07,77.65) 14.13,77.78 14.19,77.85 arc(14.29,77.99) 14.32,78.15 14.32,78.24 arc(14.03,79.66) 13.23,80.87 12.02,82.08 arc(11.1,82.69) 10.03,82.91 9.44,82.91
  BOTTOM w0.178: R63.1 9.14,82.64 arc(9.22,82.82) 9.4,82.89 ; J7.1 9.77,65.39 arc(11.43,64.7) 12.12,63.04 12.12,58.3 arc(12.29,57.9) 12.69,57.73
N17097514: length 4
  TOP w0.508: S4.9 59.41,22.5 v1(59.56,22.35)
  BOTTOM w0.508: R43.2 R55.1 v1(59.56,22.35)
N17097522: length 4
  TOP w0.508: v1(62.36,22.35) 61.95,22.76 S4.11
  BOTTOM w0.508: v1(62.36,22.35) R54.1 R42.2
N17097524: length 4.1
  TOP w0.508: v1(65.15,22.35) 64.49,23.01 S4.13
  BOTTOM w0.508: v1(65.15,22.35) R53.1 R41.2
N17097526: length 4.2
  TOP w0.508: v1(49.02,22.35) 49.25,22.58 S4.1
  BOTTOM w0.508: v1(49.02,22.35) 48.26,21.59 R59.1 R47.2
N17097528: length 4
  TOP w0.508: v1(53.85,22.35) 54.33,22.83 S4.5
  BOTTOM w0.508: v1(53.85,22.35) R57.1 R45.2
N17097530: length 4.1
  TOP w0.508: S4.3 51.79,22.71 v1(51.43,22.35)
  BOTTOM w0.508: R46.2 R58.1 51.05,21.97 v1(51.43,22.35)
N17097532: length 3.9
  TOP w0.508: S4.7 56.87,22.58 v1(56.64,22.35)
  BOTTOM w0.508: v1(56.64,22.35) R56.1 R44.2
N17097556: length 4.2
  TOP w0.508: v1(67.94,22.35) 67.03,23.27 S4.15
  BOTTOM w0.508: v1(67.94,22.35) R52.1 R40.2
N17103018: length 75.7
  TOP w0.152: 8.45,25.5 10.68,25.5 arc(13.61,26.72) 14.83,29.65 14.83,66.19 arc(15.35,68.85) 16.86,71.1 20.03,74.28 arc(22.2,75.72) 24.75,76.23 25.67,76.23 ; C11.1 26.9,76.06 arc(26.71,76.18) 26.49,76.23 25.67,76.23 ; 25.67,76.23 R49.1
  TOP w0.178: J6.1 5.45,17.77 arc(7.12,18.46) 7.8,20.12 7.8,24.96 arc(7.96,25.33) 8.34,25.49
N17103031: length 75.7
  TOP w0.152: 8.37,26.01 10.68,26.01 arc(13.25,27.08) 14.32,29.65 14.32,66.19 arc(14.88,69.04) 16.5,71.46 19.67,74.63 arc(22,76.19) 24.75,76.74 25.67,76.74 ; 25.67,76.74 26.49,76.74 arc(26.71,76.78) 26.9,76.91 C9.1 ; 25.67,76.74 R48.1
  TOP w0.178: J5.1 5.45,33.64 arc(7.12,32.95) 7.8,31.29 7.8,26.59 arc(7.97,26.19) 8.37,26.02
N17121993: length 2.3
  TOP w0.254: U6.6 70.23,140.64 70.64,141.05
  TOP w0.508: R77.2 70.95,141.36 70.64,141.05
N17123672: length 10.5
  TOP w0.178: Y1.2 30.55,122.88 32.12,124.45 C19.1 34.42,124.84 U4.70
N17123682: length 8.1
  TOP w0.178: Y1.1 30.55,127.06 31.87,125.74 C20.1 34.44,125.34 U4.69
N17132631:
  vias: v1(30.39,146.47) v1(30.47,148.42)
N17133396: length 1.4
  TOP w0.305: C15.1 35.31,148.08 35,147.77 U2.3
N17138963: length 3.7
  TOP w0.178: U1.49 32.21,85.29 31.8,85.7 31.8,85.85 v1(31.78,85.88)
  BOTTOM w0.381: v1(31.78,85.88) 31.8,85.9 31.8,86.18 32.26,86.64 C2.2
N17143987: length 3
  TOP w0.254: U1.64 32.07,77.79 31.67,77.39 v1(31.67,77.06)
  BOTTOM w0.508: v1(31.67,77.06) 31.67,76.76 C8.2
N17154309: length 1.7
  TOP w0.178: R2.1 18.37,13.41 LED2.2
N17160541: length 2.6
  TOP w0.33: R76.1 61.98,142.41 61.93,142.36 U5.8
N17174458: length 3.8
  TOP w0.254: U1.33 41.65,86.44
  TOP w0.305: 41.65,86.44 v1(41.65,87.78)
  TOP w0.508: R3.2 41.65,87.84 v1(41.65,87.78)
  BOTTOM w0.508: v1(41.65,87.78) 41.65,87.98 42.19,88.52 R3.2
N17176193: length 1.5
  BOTTOM w0.381: C1.2 44.94,88.38 R4.2
N17179271: length 0.1
  TOP w0.178: U8.9 77.29,171.94
N17179285: length 3.2
  TOP w0.254: R104.1 78.59,171.83 v1(78.16,171.4) 78.08,171.32 U8.8
  BOTTOM w0.254: R104.1 78.59,171.83 v1(78.16,171.4)
N17180621: length 1.9
  TOP w0.254: U8.7 78.1,170.82 78.61,170.31 C51.1
N17181839: length 2.2
  TOP w0.229: 73.61,171.32 U8.3
  TOP w0.33: R105.1 72.95,171.07 73.2,171.32 73.61,171.32
N17182034: length 0.1
  TOP w0.178: U8.5 74.34,170.2
  vias: v1(72.8,169.04) v1(73.36,168.33) v1(73.71,169.93) v1(74.04,169.16)
N17191311: length 1.4
  TOP w0.508: LED3.2 62.88,173.74 62.98,173.64 R98.1
N17214967:
  vias: v1(75.51,158.32) v1(75.46,157.66) v1(76.71,152.96) v1(77.98,152.96) v1(79.17,154.23) v1(79.25,152.96) v1(80.52,152.96)
N17217834: length 3.1
  TOP w0.305: U9.22 73.9,151.96
  TOP w0.381: R114.2 74.87,151.26 74.17,151.96 73.9,151.96
N17220662: length 2.3
  TOP w0.33: U9.28 72.9,158.02 R111.2
N17221888: length 1.9
  TOP w0.178: v1(74.45,154.43) 74.45,154.31 74.1,153.96 v1(74.1,153.91)
  TOP w0.254: U9.25 v1(74.1,153.91)
N17228595: length 2.3
  TOP w0.254: U9.10 v1(66.04,150.01)
  BOTTOM w0.381: v1(66.04,150.01) 66.34,150.01 66.75,149.61 R116.2
N17228599: length 3.5
  TOP w0.254: R115.2 65.02,155.22 66.33,153.91 U9.4
N17278417: length 4.9
  TOP w0.635: S1.5 v1(54.31,6.4)
  BOTTOM w0.508: v1(54.31,6.4) 54.81,6.91 R26.1 R10.2
N17278419: length 4.8
  TOP w0.635: S1.9 v1(59.39,6.4)
  BOTTOM w0.508: R24.1 R8.2 59,6.78 v1(59.39,6.4)
N17278425: length 4.8
  TOP w0.635: S1.3 v1(51.77,6.4)
  BOTTOM w0.508: v1(51.77,6.4) 52.02,6.65 R27.1 R11.2
N17278439: length 4.9
  TOP w0.635: S1.7 v1(56.85,6.4)
  BOTTOM w0.508: v1(56.85,6.4) 56.21,7.04 R9.2 R25.1
N17278441: length 4.7
  TOP w0.635: S1.13 v1(64.47,6.4)
  BOTTOM w0.508: R22.1 R6.2 64.59,6.53 v1(64.47,6.4)
N17278443: length 4.7
  TOP w0.635: S1.11 v1(61.93,6.4)
  BOTTOM w0.508: v1(61.93,6.4) 61.8,6.53 R7.2 R23.1
N17278445: length 4.8
  TOP w0.635: S1.15 v1(67.01,6.4)
  BOTTOM w0.508: v1(67.01,6.4) 67.39,6.78 R5.2 R21.1
N17278449: length 4.7
  TOP w0.635: S1.1 v1(49.23,6.4)
  BOTTOM w0.508: R12.2 R28.1 v1(49.23,6.4)
N17278561: length 4.6
  TOP w0.635: S2.9 v1(35.81,6.4)
  BOTTOM w0.508: R16.2 R32.1 36.07,6.65 v1(35.81,6.4)
N17278569: length 4.7
  TOP w0.635: S2.11 v1(38.35,6.4)
  BOTTOM w0.508: v1(38.35,6.4) 38.86,6.91 R31.1 R15.2
N17278593: length 4.7
  TOP w0.635: S2.13 v1(40.89,6.4)
  BOTTOM w0.508: v1(40.89,6.4) 40.26,7.04 R14.2 R30.1
N17278595: length 4.8
  TOP w0.635: S2.1 v1(25.65,6.4)
  BOTTOM w0.508: R20.2 R36.1 24.89,7.16 v1(25.65,6.4)
N17278597: length 4.6
  TOP w0.635: S2.5 v1(30.73,6.4)
  BOTTOM w0.508: v1(30.73,6.4) 30.48,6.65 R34.1 R18.2
N17278599: length 4.7
  TOP w0.635: S2.3 v1(28.19,6.4)
  BOTTOM w0.508: v1(28.19,6.4) 27.69,6.91 R35.1 R19.2
N17278601: length 4.5
  TOP w0.635: S2.7 v1(33.27,6.4)
  BOTTOM w0.508: v1(33.27,6.4) R33.1 R17.2
N17278603: length 4.6
  TOP w0.635: S2.15 v1(43.43,6.4)
  BOTTOM w0.508: v1(43.43,6.4) 43.05,6.78 R13.2 R29.1
N17395731: length 1.6
  TOP w0.178: LED1.2 R1.1
N17653350: length 2.9
  TOP w0.178: U5.1 61.33,137.81 61.72,137.41 R120.2
N171178020: length 1.8
  TOP w0.178: R75.2 52.82,113.14 52.55,113.41 Q1.3
N173796350: length 1.4
  TOP w0.178: LED4.1 54.22,114.54 54.12,114.44 R75.1
N175788770: length 1.8
  BOTTOM w0.635: R87.1 J14.6

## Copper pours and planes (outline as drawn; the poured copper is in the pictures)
+5V on TOP: 63.83,162.26 60.83,159.26 60.76,159.26 60.05,158.55 60.05,147.57 60.38,147.24 65.23,147.24 65.63,147.65 65.63,148.23 65.91,148.51 68.07,148.51 68.12,148.56 68.12,149.5 68.1,149.53 65.68,149.53 65.3,149.15 63.7,149.15 63.5,149.35 63.5,152.98 63.65,153.14 65.28,153.14 65.96,152.45 68.1,152.45 68.12,152.48 68.12,153.42 68.1,153.44 66.5,153.44 66.43,153.5 66.13,153.5 65.2,154.43 64.31,154.43 64.06,154.69 64.06,157.99 64.69,158.62 67.18,158.62 67.82,159.26 67.82,165.23 67.56,165.48 67.56,168.02 67.82,168.28 71.18,168.28 71.18,171.76 71.4,171.98 73.33,171.98 73.63,171.68 74.78,171.68 74.78,172.95 74.5,173.23 72.01,173.23 71.5,173.74 64.13,173.74 63.83,173.43
+5V on BOTTOM: 67.47,164.88 67.47,167.92 71.63,167.92 71.63,173.23 70.48,174.37 64.35,174.37 63.69,173.71 63.69,164.88
+5V on BOTTOM: 60.08,155.24 60.08,148.02 63.5,148.02 63.5,148.05 65.78,148.05 66.27,148.54 66.27,149.45 66.13,149.6 63.93,149.6 63.5,150.03 63.5,151.72 64.3,152.52 66.59,152.52 66.9,152.83 66.9,153.74 66.13,154.5 63.87,154.5 63.5,154.88 63.5,155.24
VBUS on TOP: 23.55,151.18 23.55,148.42 27.85,148.42 28.55,147.73 29.82,147.73 29.92,147.83 29.92,148.79 29.44,149.28 29.44,150.19 28.45,151.18
VBUS on TOP: 11.56,150.53 11.56,148.34 14.32,148.34 14.32,150.53
VBUS on BOTTOM: 11.33,152.43 11.33,148.36 27.51,148.36 27.51,152.43
VDD12 on TOP: 80.52,175.97 80.52,173.39 80.57,173.34 82.95,173.34 83.24,173.06 88.96,173.06 88.96,175.97
VDD12 on BOTTOM: 80.49,176.28 80.49,173.36 81.94,173.36 82.32,172.97 88.85,172.97 89.03,173.15 89.03,176.53 88.72,176.83 81.05,176.83
VDD12 on BOTTOM: 35,68.08 35,65.05 37.01,65.05 37.01,68.08
VDD12 on BOTTOM: 20.3,87.14 20.3,85.34 22.15,85.34 22.15,87.14
VDD12 on BOTTOM: 53.26,94.11 53.26,92.13 55.47,92.13 55.47,94.11
VDD12 on BOTTOM: 23.68,68.66 23.68,66.79 26.12,66.79 26.12,68.66
VDD12 on BOTTOM: 42.54,69.98 42.54,67.95 40.39,67.95 40.39,69.98
VDD12 on POWER: 15.85,58.52 15.85,127.51 2.03,127.51 2.03,166.78 11.1,166.78 11.1,176.28 88.77,176.28 88.77,163.8 73.36,163.8 73.36,157.12 66.22,157.12 66.22,152.02 26.31,152.02 26.31,106.4 48.79,106.4 48.79,95.76 48.77,95.76 48.77,94.82 55.7,94.82 55.7,92.38 53.59,90.27 28.35,90.27 26.57,88.49 26.57,80.95 22.58,80.95 22.58,68.45 40.06,68.45 40.06,76.17 47.29,76.17 47.29,58.52
VDD12_LVDS on BOTTOM: 42.8,75.05 42.73,75.05 42.37,75.41 42.37,78.39 42.6,78.61 42.6,79.4 42.57,79.43 42.57,81.43 42.58,81.45 42.58,82.74 42.77,82.93 44.57,82.93 45.3,83.67 45.3,85.53 45.21,85.62 41.58,85.62 41.58,86.59 47.12,86.59 47.14,86.56 47.14,83.67 47.19,83.62 47.19,81.34 47.18,81.25 47.18,70.55 45.21,68.58 43.31,68.58 43.05,68.83 43.05,74.8
VDD12_PIN33 on TOP: 50.42,91.17 50.42,90.23 50.76,89.89 53.27,89.89 53.57,90.19 53.57,91.4 53.38,91.59 50.85,91.59
VDD12_PIN33 on BOTTOM: 45.8,89.41 54,89.41 54.91,90.32 54.91,91.54 49.89,91.54 49.83,91.49 49,92.33 46.18,92.33 45.72,91.87 45.72,90.65 45.54,90.47 43.51,90.47 43.38,90.35 43.38,89.03 43.54,88.87 45.26,88.87
VDD18 on TOP, BOTTOM: 80.9,158.5 80.9,155.57 81.28,155.19 81.28,153.8 81.41,153.67 88.65,153.67 88.65,158.5
VDD18 on POWER: 45.49,116.08 45.49,134.11 67.49,134.11 67.49,155.85 74.63,155.85 74.63,162.53 88.77,162.53 88.77,151.71 78.44,151.71 78.44,126.87 56.08,126.87 56.08,119.61 85.14,119.61 85.14,116.08
VDD33 on TOP, BOTTOM: 80.92,149.35 80.92,146.05 88.34,146.05 88.34,149.15 88.14,149.35
VDD33 on BOTTOM: 58.45,92.1 59.99,92.1 59.99,93.12 59.23,93.88 58.72,93.88 58.37,93.52 58.37,92.18
VDD33 on POWER: 50.06,95.91 50.06,106.4 82.5,106.4 82.5,112.62 86.41,112.62 86.41,114.7 86.41,114.7 86.41,120.88 57.35,120.88 57.35,125.6 80.98,125.6 80.98,150.44 90.04,150.44 90.04,166.37 100.2,166.37 100.2,88.98 66.47,88.98 63.37,92.08 59.54,92.08 58.19,93.42 58.19,95.91
VDD33_UC on TOP: 53.82,129.51 53.82,127 55.3,127 55.3,129.51
VDD33_UC on TOP: 38.51,150.6 38.51,146.89 44.58,146.89 44.58,150.6
VDD33_UC on BOTTOM: 52.11,144.51 53.77,142.85 53.77,139.83 53.06,139.12 53.06,138.33 53.29,138.1 55.27,138.1 60.86,143.69 66.98,143.69 69.01,141.66 69.01,139.24 69.14,139.12 69.75,139.12 69.95,139.32 69.95,140.44 70.94,141.43 70.94,144.45 68.33,147.07 58.67,147.07 54.15,151.59 32.92,151.59 31.18,149.85 31.18,145.92 30.28,145.92 30.28,130.89 32.59,128.57 37.26,128.57 38.84,127 38.84,121.41 37.67,120.24 36.3,120.24 32.44,116.38 20.57,116.38 20.24,116.71 20.15,116.62 18.87,116.62 18.72,116.48 18.72,113.71 20.29,112.14 34.01,112.14 35.38,113.51 47.22,113.51 48.12,112.61 55.64,112.61 56.16,113.13 56.16,123.44 54.66,124.94 54.66,126.34 55.27,126.95 55.27,129.67 54.81,130.12 52.7,130.12 52.04,129.46 52.04,118.47 49.95,116.37 47.59,116.37 47.27,116.69 47.27,117.5 47.07,117.7 46.13,117.7 45.64,118.19 45.64,120.04 46.51,120.9 49.47,120.9 49.75,121.18 49.75,129.9 46.91,132.74 38.13,132.74 35.15,135.71 35.15,142.06 37.6,144.51 ; 2 cut-outs
VDD33C on TOP: 68.84,8.7 68.84,9.97 22.79,9.97 22.79,13.42 68.57,13.42 68.57,18.8 46.74,18.8 46.35,19.18 46.35,20.57 46.77,20.99 77.45,20.99 78.6,19.84 90.87,19.84 91.41,19.3 91.44,19.3 92.46,18.29 92.46,10.7 90.45,8.7
VDD33C on TOP: 55.9,91.42 55.9,89.71 55.99,89.61 58.06,89.61 58.35,89.89 58.35,91.31 58.12,91.53 56.01,91.53
VDD33C on BOTTOM: 55.91,91.64 55.91,89.59 59.44,89.59 59.44,91.64
VDD33C on BOTTOM: 45.05,83.72 45.05,85.05 44.68,85.42 42.98,85.42 42.72,85.17 42.72,83.21 42.8,83.13 44.47,83.13
VDD33C on BOTTOM: 33.09,81.55 33.09,82.3 31.56,82.3 31.56,81.55
VDD33C on POWER: 83.74,14.96 83.74,66.57 48.56,66.57 48.56,78 34.98,78 34.47,78.51 34.47,81.08 28.65,81.08 28.09,81.64 28.09,87.12 29.01,88.04 37.62,88.04 37.95,87.71 54.56,87.71 55.7,88.85 55.7,90.63 56.46,91.39 58.42,91.39 59.31,90.5 63.45,90.5 66.24,87.71 100.2,87.71 100.2,14.96
VDD_12.0V_EXTERNAL on TOP: 16.38,161.49 23.09,161.49 23.8,160.78 26.11,160.78 26.16,160.83 26.16,161.8 26.09,161.87 24.05,161.87 23.44,162.48 23.44,163.04 23.19,163.3 19.61,163.3 18.69,164.21 18.69,166.09 17.45,167.34 10.74,167.34 10.03,166.62 10.03,157.71 10.77,156.97 15.54,156.97 15.85,157.28 15.85,160.96
VDD_12.0V_EXTERNAL on BOTTOM: 10.64,162.38 10.64,157.66 11.33,156.97 23.44,156.97 24.99,158.52 24.99,162.86 23.8,164.06 20.88,164.06 19.84,165.1 19.84,166.45 18.59,167.69 11,167.69 10.41,167.11 10.41,162.61
VDD_I2C on TOP: 86.28,133.5 84.58,135.2 70.05,135.2 69.93,135.33 69.93,135.97 70.23,136.27 70.61,136.27 70.87,136.02 72.19,136.02 74.02,137.85 75.76,137.85 77.88,139.97 77.88,142.78 78.17,143.07 79.89,143.07 80.31,142.65 80.31,138.99 81.46,137.85 89.84,137.85 91.57,136.12 91.57,131.83 92.74,130.66 92.74,124.08 90.75,122.1 90.75,116.97 89.74,115.95 86.23,115.95 85.79,116.4 85.79,118.43 86.28,118.92
VDDIO on TOP: 27.61,111.66 27.61,109.58 32.49,109.58 33.48,108.59 35.71,108.59 35.81,108.69 35.81,110.97 35.13,111.66
VDDIO on BOTTOM: 36.22,109.75 36.22,111.53 35.86,111.89 27.97,111.89 27.23,111.15 27.23,109.8 27.61,109.42 35.89,109.42
VDDIO on BOTTOM: 79.76,113.54 78.36,113.54 78.36,112.65 81.53,112.65 82.04,113.16 83.82,113.16 84.45,113.79 84.45,114.68 83.69,115.44 80.52,115.44 79.76,114.68
VDDIO on POWER: 27.58,107.67 27.58,150.37 66.22,150.37 66.22,135.38 44.22,135.38 44.22,114.33 76.56,114.33 77.43,115.19 85.33,115.19 85.33,113.56 81.1,113.56 81.1,107.67
VDDIOC on TOP: 79.8,110.88 79.8,109.11 81.27,109.11 81.27,110.88
VDDIOC on BOTTOM: 34.26,76.53 34.26,75.26 33.93,74.93 29.69,74.93 28.02,73.25 28.02,55.65 30.99,52.68 66.52,52.68 66.55,52.71 77.98,52.71 82.8,57.53 82.8,107.31 81.41,108.71 81.41,112.14 81.28,112.27 78.23,112.27 77.98,112.01 77.98,110.24 78.23,109.98 78.23,107.06 69.9,98.73 69.9,63.37 34.28,63.37 34.28,71.23 35.46,72.42 35.46,74.57 36.02,75.13 36.02,75.82 36.3,76.1 36.3,76.63 36.22,76.71 34.44,76.71
VDDL12C on BOTTOM: 35.79,74.47 35.79,68.69 37.35,68.69 37.35,64.14 68.4,64.14 68.4,103.56 41.3,103.56 36.07,98.32 36.07,98.27 35.15,97.36 35.15,87.6 34.77,87.22 34.77,86.39 34.82,86.33 37.49,86.33 38.18,87.02 38.18,88.39 38.51,88.72 40.34,88.72 41.05,89.43 41.05,93.78 43.51,96.24 60.6,96.24 62.76,94.08 62.76,74.3 55.68,67.21 39.96,67.21 39.55,67.62 39.55,69.7 38.89,70.36 37.59,70.36 37.35,70.6 37.35,72.72 37.66,73.03 37.66,76.52 37.49,76.68 36.75,76.68 36.55,76.47 36.55,76.23 36.38,76.07 36.38,75.07
VDDP12_0 on BOTTOM: 22.9,86.66 22.64,86.39 22.64,85.31 22.99,84.95 26.64,84.95 27.01,84.58 30.99,84.58 31.78,83.79 33.02,83.79 33.2,83.97 33.2,85.8 33.17,85.83 31.95,85.83 31.75,85.62 31.75,85.39 29.77,85.39 28.69,86.48 24.34,86.48 24.16,86.66
VDDP12_1 on TOP: 24.14,72.29 24.14,69.47 26.09,69.47 26.09,72.29
VDDP12_1 on BOTTOM: 31.58,81.54 31.94,81.54 32.15,81.33 33.12,81.33 33.17,81.28 33.17,78.08 33.12,78.03 33.12,77.09 32.97,76.94 32.18,76.94 31.93,77.19 31.93,77.37 31.83,77.47 31.52,77.47 31.39,77.6 31.39,81.36
VDDP12_1 on BOTTOM: 24.16,72.57 24.16,69.14 26.14,69.14 26.14,72.57
VDDP12_1 on POWER: 32.92,80.01 24.21,80.01 24.21,69.49 32.92,69.49
VSS on TOP: 35.69,105.53 35.69,107.76 33,107.76 31.92,108.84 28.18,108.84 27.58,108.24 27.58,106.17 28.23,105.53
VSS on TOP: 63.75,152.58 63.75,149.66 63.86,149.56 65.41,149.56 65.48,149.63 65.48,150.06 65.84,150.42 66.37,150.42 66.45,150.5 68.12,150.5 68.15,150.52 68.15,150.8 68.1,150.85 66.57,150.85 66.27,151.16 66.27,151.79 65.33,152.73 63.91,152.73
VSS on TOP: 32.07,145.3 33.33,145.3 33.49,145.46 33.49,150.92 33.11,151.3 32.2,151.3 31.95,151.05 31.95,145.42
VSS on TOP: 19.43,164.34 23.72,164.34 24,164.62 24,164.74 24.18,164.92 25.65,164.92 25.88,164.69 25.88,163.86 26.59,163.14 26.59,157.02 26.06,156.49 25.48,156.49 25.2,156.21 25.2,154.46 24.87,154.13 21.51,154.13 21.23,154.41 21.23,156.03 21.13,156.13 19.76,156.13 19.58,155.96 19.58,153.31 20.02,152.88 29.74,152.88 30.38,153.52 30.38,156.26 29.9,156.74 29.9,169.77 29.16,170.51 20.07,170.51 19.43,169.88
VSS on TOP: 38.96,145.92 38.96,143.26 44.58,143.26 44.58,145.92
VSS on TOP: 25.12,143.18 28.63,143.18 28.63,146.48 24.74,146.48 24.71,146.45 24.71,143.59
VSS on TOP: 55.88,94.16 55.88,92.05 57.48,92.05 57.48,94.16
VSS on TOP: 51.18,94.16 51.18,92.1 52.96,92.1 52.96,94.16
VSS on TOP: 2.54,0.76 1.28,1.28 0.76,2.54 0.76,9.55 0,10.32 0,119.26 0.76,120.02 0.76,175.26 0.8,175.61 0.8,175.61 0.76,175.26 1.28,176.52 2.54,177.04 99.31,177.04 100.4,176.51 100.84,175.39 100.84,2.54 100.32,1.28 99.06,0.76 ; 62 cut-outs
VSS on TOP: 1.73,136.07 1.73,139.6 6.91,139.6 7.11,139.8 9.63,139.8 9.63,136.33 9.37,136.07
VSS on TOP: 96.98,158.83 96.98,156.03 99.49,156.03 99.49,158.83
VSS on TOP: 64.59,157.94 64.59,156.77 67.59,156.77 68.38,155.98 68.38,145.64 68.83,145.19 78.31,145.19 78.59,145.47 78.59,146.86 78.33,147.12 76.23,147.12 75.74,147.6 75.74,147.93 75.56,148.11 74.57,148.11 74.32,147.85 74.32,147.29 74.09,147.07 72.01,147.07 71.86,147.22 71.86,158.98 72.26,159.38 75.77,159.38 76.02,159.13 76.02,157.35 75.51,156.84 74.93,156.84 74.8,156.72 74.8,155.19 75.06,154.94 75.95,154.94 77.22,156.21 78.99,156.21 79.5,156.72 79.5,158.12 80.64,159.26 82.55,159.26 83.06,159.77 83.06,161.8 82.55,162.31 69.09,162.31 68.33,161.54 68.33,158.98 67.44,158.09 64.74,158.09
VSS on TOP: 48.69,93.07 48.69,94.33 48.52,94.5 47.77,94.5 47.65,94.38 47.65,93.04 47.83,92.86 48.49,92.86
VSS on TOP, BOTTOM: 21.21,72.64 21.21,70.87 23.62,70.87 23.62,72.64
VSS on BOTTOM: 37.9,74.42 37.9,72.77 37.72,72.59 37.72,70.84 37.9,70.66 40.03,70.66 40.03,74.42
VSS on BOTTOM: 33.63,77.95 33.3,77.95 33.3,77.04 34.21,77.04 34.21,77.14 40.08,77.14 40.08,76.73 42.01,76.73 42.01,78.84 42.27,78.84 42.27,85.34 41.33,85.34 41.33,86.94 42.19,86.94 42.19,87.66 38.56,87.66 38.56,85.85 34.32,85.85 34.32,87 33.63,87
VSS on BOTTOM: 31.86,108.15 31.86,104.04 36.14,104.04 36.14,108.15
VSS on BOTTOM: 77.6,109.35 77.6,112.9 74.68,112.9 74.68,108.08 77.72,108.08 77.98,108.33 77.98,108.97
